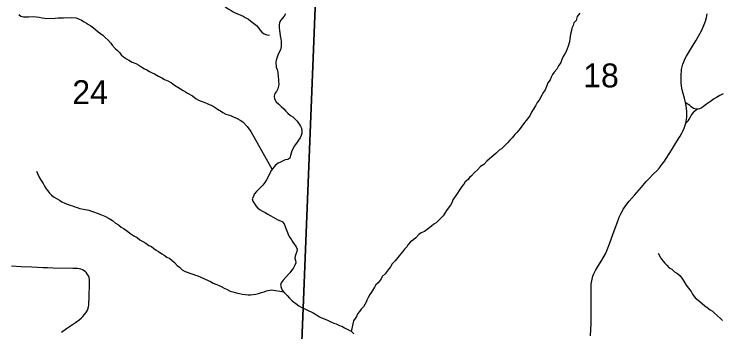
# Model space of a CAD drawing. Extents: x -3.3 to 34, y 0 to 56.8.
# Drawn here: x -1.801 to -0.562, y 32.848 to 33.404 of the extents above; entities that cross this region are included whole.
import ezdxf

# ---------------------------------------------------------------- set-up
doc = ezdxf.new("R2010")
doc.units = 0
for name, color, linetype in [('GM_X_Corporation', 7, 'Continuous'), ('GM_X_County_Road', 7, 'Continuous'), ('GM_X_Section_Text', 7, 'Continuous'), ('GM_X_Township_Road', 7, 'Continuous'), ('GT_Project_Soil_Layers', 7, 'Continuous')]:
    doc.layers.add(name, color=color, linetype=linetype)

msp = doc.modelspace()

# ---------------------------------------------------------------- linework, layer by layer
at = {"layer": 'GM_X_Corporation'}
for points in [[(-2.2828, 33.7097), (-1.2628, 33.6793), (-1.3017, 32.7146), (-2.3198, 32.7465)], [(-1.2628, 33.6793), (-0.2543, 33.6541), (-0.2878, 32.6826), (-1.3017, 32.7146)]]:
    msp.add_lwpolyline(points, close=True, dxfattribs=at)
at = {"layer": 'GM_X_County_Road'}
msp.add_lwpolyline([(-0.7912, 32.8413), (-0.7905, 32.8627), (-0.7906, 32.9051), (-0.7905, 32.9233), (-0.7904, 32.9274), (-0.7902, 32.9318), (-0.7899, 32.9347), (-0.7888, 32.9404), (-0.7873, 32.9455), (-0.7855, 32.9501), (-0.7826, 32.9555), (-0.7757, 32.9671), (-0.7719, 32.9735), (-0.7655, 32.9848), (-0.7622, 32.9921), (-0.7581, 33.0023), (-0.7518, 33.0205), (-0.7455, 33.0375), (-0.741, 33.0489), (-0.7383, 33.0547), (-0.7363, 33.059), (-0.734, 33.0632), (-0.7321, 33.0661), (-0.7299, 33.0693), (-0.7239, 33.0768), (-0.7146, 33.0877), (-0.7023, 33.1018), (-0.6939, 33.1114), (-0.6889, 33.1169), (-0.6812, 33.1246), (-0.6756, 33.1301), (-0.6709, 33.1354), (-0.6666, 33.1411), (-0.6633, 33.1455), (-0.6496, 33.1664), (-0.6408, 33.1808), (-0.6343, 33.191), (-0.6315, 33.1958), (-0.6296, 33.1996), (-0.6274, 33.2047), (-0.6255, 33.2102), (-0.6245, 33.2137), (-0.6238, 33.2173), (-0.6234, 33.2205), (-0.623, 33.2241), (-0.6227, 33.2291), (-0.6229, 33.2341), (-0.6235, 33.2394), (-0.6241, 33.2443), (-0.6252, 33.2496), (-0.6271, 33.2575), (-0.6294, 33.2655), (-0.631, 33.2719), (-0.6316, 33.2746), (-0.6322, 33.2789), (-0.6328, 33.2842), (-0.633, 33.2895), (-0.6328, 33.2991), (-0.6323, 33.3039), (-0.6319, 33.3075), (-0.631, 33.3122), (-0.6297, 33.3167), (-0.6283, 33.3208), (-0.6267, 33.3242), (-0.6232, 33.3311), (-0.6144, 33.3457), (-0.6073, 33.3577), (-0.6023, 33.3661), (-0.5994, 33.3714), (-0.5973, 33.3754), (-0.5936, 33.3836), (-0.5904, 33.3921), (-0.5885, 33.3986), (-0.5873, 33.4047)], dxfattribs=at)
at = {"layer": 'GM_X_Township_Road'}
for points in [[(-0.5593, 33.2647), (-0.5649, 33.2621), (-0.571, 33.2587), (-0.5763, 33.2554), (-0.5813, 33.2518), (-0.5884, 33.2466), (-0.5958, 33.2411), (-0.598, 33.2399), (-0.6006, 33.2388), (-0.6029, 33.2383), (-0.6052, 33.238)], [(-0.6052, 33.238), (-0.6086, 33.2384), (-0.611, 33.2393), (-0.6129, 33.2403), (-0.615, 33.242), (-0.6175, 33.2443), (-0.6197, 33.2461), (-0.622, 33.2476), (-0.6252, 33.2496)], [(-0.6245, 33.2137), (-0.6205, 33.2177), (-0.6186, 33.2204), (-0.6164, 33.2247), (-0.615, 33.2272), (-0.6134, 33.2296), (-0.6113, 33.2322), (-0.6093, 33.2343), (-0.6052, 33.238)], [(-1.7177, 32.8474), (-1.7087, 32.8541), (-1.6935, 32.8647), (-1.6871, 32.8695), (-1.6833, 32.8722), (-1.6802, 32.8752), (-1.6774, 32.8784), (-1.675, 32.8814), (-1.6728, 32.8851), (-1.6716, 32.8879), (-1.6707, 32.8922), (-1.6701, 32.8957), (-1.6697, 32.8999), (-1.6694, 32.9063), (-1.6692, 32.9151), (-1.6689, 32.9257), (-1.6686, 32.9348), (-1.6688, 32.9392), (-1.6695, 32.9433), (-1.6706, 32.9465), (-1.6721, 32.9489), (-1.6738, 32.9514), (-1.6756, 32.9532), (-1.6783, 32.9553), (-1.6812, 32.9568), (-1.6839, 32.9578), (-1.6868, 32.9585), (-1.6897, 32.959), (-1.6977, 32.9594), (-1.7331, 32.9598), (-1.7422, 32.9601), (-1.7497, 32.9604), (-1.7697, 32.9613), (-1.7881, 32.9622), (-1.8053, 32.963)]]:
    msp.add_lwpolyline(points, dxfattribs=at)
at = {"layer": 'GT_Project_Soil_Layers'}
for points in [[(-1.4349, 33.4207), (-1.4299, 33.4166), (-1.4257, 33.414), (-1.4207, 33.411), (-1.4169, 33.4084), (-1.4123, 33.4062), (-1.4078, 33.4044), (-1.404, 33.4029), (-1.3998, 33.4011), (-1.3959, 33.3988), (-1.3906, 33.3959), (-1.386, 33.3921), (-1.3814, 33.3888), (-1.3764, 33.3847), (-1.3729, 33.3805), (-1.3702, 33.3768), (-1.3671, 33.3727), (-1.3629, 33.3697), (-1.3584, 33.3682), (-1.3538, 33.3675)], [(-1.7926, 33.4036), (-1.7888, 33.401), (-1.7842, 33.3995), (-1.7793, 33.3996), (-1.7755, 33.4), (-1.7668, 33.4002), (-1.7619, 33.3995), (-1.7569, 33.3992), (-1.7516, 33.3981), (-1.747, 33.3974), (-1.7432, 33.3971), (-1.7288, 33.3973), (-1.7235, 33.3977), (-1.719, 33.3978), (-1.7141, 33.3982), (-1.7, 33.3984), (-1.6921, 33.3978), (-1.6879, 33.3963), (-1.6829, 33.3941), (-1.6779, 33.3911), (-1.6741, 33.3885), (-1.6703, 33.3863), (-1.6661, 33.3837), (-1.6619, 33.3807), (-1.658, 33.3777), (-1.6534, 33.3736), (-1.6492, 33.3706), (-1.6454, 33.3677), (-1.6415, 33.3635), (-1.6358, 33.3587), (-1.6312, 33.3538), (-1.6288, 33.35), (-1.6235, 33.3444), (-1.6196, 33.3407), (-1.6154, 33.3369), (-1.6131, 33.3332), (-1.6092, 33.3298), (-1.6039, 33.3261), (-1.6, 33.3238), (-1.5939, 33.3205), (-1.5878, 33.3179), (-1.5825, 33.315), (-1.5771, 33.3116), (-1.5725, 33.3087), (-1.5683, 33.3072), (-1.5634, 33.3042), (-1.5588, 33.3016), (-1.555, 33.3002), (-1.5477, 33.2961), (-1.542, 33.2927), (-1.5374, 33.2901), (-1.5317, 33.2876), (-1.5252, 33.2839), (-1.5198, 33.2801), (-1.5141, 33.2768), (-1.5091, 33.2734), (-1.5049, 33.2709), (-1.5007, 33.2686), (-1.4969, 33.266), (-1.4881, 33.2612), (-1.4819, 33.2564), (-1.4777, 33.2541), (-1.4732, 33.2523), (-1.4694, 33.2508), (-1.4636, 33.2483), (-1.4594, 33.2464), (-1.4556, 33.2449), (-1.4507, 33.2424), (-1.4468, 33.2401), (-1.443, 33.2371), (-1.4392, 33.2353), (-1.4354, 33.2323), (-1.43, 33.2294), (-1.4262, 33.2279), (-1.422, 33.2268), (-1.4182, 33.225), (-1.4136, 33.2235), (-1.409, 33.2209), (-1.4048, 33.2187), (-1.4002, 33.2157), (-1.3925, 33.2075), (-1.3864, 33.1992), (-1.3489, 33.1325)], [(-1.3255, 33.4048), (-1.3281, 33.4009), (-1.334, 33.3932), (-1.3363, 33.3894), (-1.3366, 33.3856), (-1.3369, 33.3807), (-1.3361, 33.3757), (-1.3353, 33.3716), (-1.3348, 33.3663), (-1.3336, 33.361), (-1.3332, 33.3568), (-1.3331, 33.3522), (-1.3334, 33.3477), (-1.3345, 33.342), (-1.3371, 33.337), (-1.3389, 33.3328), (-1.3404, 33.329), (-1.3418, 33.324), (-1.3425, 33.3202), (-1.3416, 33.3115), (-1.3401, 33.3073), (-1.3392, 33.3024), (-1.3384, 33.2948), (-1.3379, 33.2903), (-1.3375, 33.2865), (-1.3374, 33.2819), (-1.3378, 33.2781), (-1.3392, 33.2735), (-1.3414, 33.2693), (-1.3444, 33.2655), (-1.3455, 33.2609), (-1.3447, 33.2564), (-1.3416, 33.2507), (-1.337, 33.2466), (-1.3331, 33.2425), (-1.3285, 33.2384), (-1.325, 33.2346), (-1.3212, 33.2309), (-1.3166, 33.2271), (-1.3128, 33.2245), (-1.3051, 33.217), (-1.3016, 33.2121), (-1.2993, 33.2084), (-1.2977, 33.2046), (-1.2969, 33.2008), (-1.2972, 33.1963), (-1.2983, 33.1921), (-1.3001, 33.1879), (-1.3027, 33.1836), (-1.3064, 33.1783), (-1.3102, 33.1733), (-1.312, 33.1691), (-1.3142, 33.1653), (-1.3157, 33.1611), (-1.3168, 33.1569), (-1.3178, 33.1523), (-1.3216, 33.15), (-1.3261, 33.1491), (-1.3299, 33.1479), (-1.3341, 33.1452), (-1.3382, 33.1433), (-1.3431, 33.1398), (-1.3505, 33.1306), (-1.3564, 33.1183), (-1.359, 33.1145), (-1.362, 33.1095), (-1.3653, 33.1049), (-1.3691, 33.1007), (-1.3728, 33.0976), (-1.3762, 33.0937), (-1.3803, 33.0891), (-1.3818, 33.0853), (-1.384, 33.0811), (-1.3828, 33.0773), (-1.3805, 33.0736), (-1.3777, 33.069), (-1.3739, 33.0645), (-1.3701, 33.0619), (-1.3659, 33.0593), (-1.3613, 33.0571), (-1.3563, 33.0541), (-1.351, 33.0512), (-1.3433, 33.0467), (-1.3391, 33.0445)], [(-0.8102, 33.4062), (-0.8147, 33.4001), (-0.8165, 33.3936), (-0.8206, 33.3894), (-0.8216, 33.3844), (-0.8239, 33.3799), (-0.8246, 33.376), (-0.8264, 33.3696), (-0.8274, 33.3612), (-0.8285, 33.3559), (-0.8306, 33.3482), (-0.8339, 33.3391), (-0.8365, 33.3349), (-0.8391, 33.3303), (-0.8417, 33.3249), (-0.8435, 33.3196), (-0.8476, 33.3142), (-0.8502, 33.3081), (-0.855, 33.3027), (-0.858, 33.2985), (-0.8606, 33.2943), (-0.862, 33.2893), (-0.8661, 33.2843), (-0.8676, 33.2805), (-0.8709, 33.2721), (-0.875, 33.2663), (-0.8768, 33.2625), (-0.8813, 33.2541), (-0.8846, 33.2495), (-0.8876, 33.2437), (-0.8917, 33.2376), (-0.8946, 33.233), (-0.898, 33.2265), (-0.9043, 33.2184), (-0.9069, 33.2146), (-0.9166, 33.2019), (-0.9203, 33.1973), (-0.9237, 33.1935), (-0.9289, 33.1877), (-0.9326, 33.1839), (-0.9368, 33.1792), (-0.9409, 33.175), (-0.9476, 33.1688), (-0.9514, 33.1665), (-0.957, 33.1604), (-0.9641, 33.1546), (-0.9686, 33.1511), (-0.9731, 33.1468), (-0.9783, 33.1414), (-0.9843, 33.1376), (-0.9896, 33.1318), (-0.9944, 33.1272), (-0.9997, 33.1214), (-1.0034, 33.1187), (-1.0056, 33.1149), (-1.0109, 33.1106), (-1.0131, 33.1068), (-1.0165, 33.1025), (-1.0217, 33.0956), (-1.0243, 33.091), (-1.0324, 33.0795), (-1.0339, 33.075), (-1.0369, 33.07), (-1.0406, 33.065), (-1.0439, 33.0604), (-1.0465, 33.0558), (-1.0495, 33.0512), (-1.0532, 33.0477), (-1.057, 33.0435), (-1.0618, 33.0389), (-1.0656, 33.0369), (-1.0701, 33.0331), (-1.075, 33.0292), (-1.0821, 33.0242), (-1.0881, 33.0214), (-1.0919, 33.0187), (-1.0971, 33.0129), (-1.1009, 33.0098), (-1.1065, 33.0056), (-1.1106, 33.001), (-1.1128, 32.9971), (-1.117, 32.9929), (-1.1207, 32.9883), (-1.1267, 32.9814), (-1.1334, 32.9725), (-1.139, 32.9675), (-1.1419, 32.9622), (-1.1457, 32.9568), (-1.1512, 32.9499), (-1.1565, 32.9449), (-1.1583, 32.941), (-1.1635, 32.9341), (-1.1673, 32.9307), (-1.1695, 32.9265)], [(-1.7616, 33.1298), (-1.7596, 33.1253), (-1.7561, 33.1181), (-1.7534, 33.1132), (-1.7499, 33.1079), (-1.7476, 33.1034), (-1.7445, 33.0989), (-1.7417, 33.0951), (-1.739, 33.091), (-1.7352, 33.0876), (-1.7306, 33.0839), (-1.7252, 33.0809), (-1.7214, 33.0787), (-1.7172, 33.0761), (-1.7119, 33.0735), (-1.7081, 33.072), (-1.7027, 33.0702), (-1.6985, 33.0691), (-1.6943, 33.0673), (-1.6902, 33.0662), (-1.6856, 33.0644), (-1.6795, 33.0633), (-1.6696, 33.0612), (-1.6654, 33.0593), (-1.6616, 33.0583), (-1.6555, 33.0561), (-1.6479, 33.0531), (-1.6418, 33.0505), (-1.6342, 33.0469), (-1.6284, 33.0431), (-1.623, 33.0387), (-1.6177, 33.0357), (-1.6135, 33.0316), (-1.6093, 33.0293), (-1.6047, 33.0264), (-1.5981, 33.0208), (-1.5913, 33.0163), (-1.5855, 33.0133), (-1.5806, 33.0096), (-1.5752, 33.0063), (-1.5699, 33.0037), (-1.5649, 32.9996), (-1.5603, 32.9974), (-1.5561, 32.994), (-1.5519, 32.9914), (-1.5477, 32.9888), (-1.5423, 32.9851), (-1.5381, 32.9825), (-1.5331, 32.9787), (-1.5281, 32.9765), (-1.5239, 32.9732), (-1.5197, 32.9694), (-1.5155, 32.9646), (-1.5113, 32.9612), (-1.5063, 32.9567), (-1.5013, 32.9541), (-1.4975, 32.9527), (-1.4929, 32.9512), (-1.4876, 32.9494), (-1.483, 32.9475), (-1.4792, 32.9461), (-1.4739, 32.9442), (-1.4674, 32.9409), (-1.4609, 32.9383), (-1.4567, 32.9361), (-1.4521, 32.9335), (-1.4475, 32.9317), (-1.4418, 32.9291), (-1.4372, 32.9273), (-1.433, 32.9247), (-1.4277, 32.9225), (-1.4223, 32.9195), (-1.4178, 32.9181), (-1.4136, 32.917), (-1.4098, 32.9159), (-1.406, 32.9152), (-1.401, 32.9145), (-1.3957, 32.9134), (-1.3908, 32.9131), (-1.3866, 32.9132), (-1.3824, 32.9136), (-1.3775, 32.9144), (-1.373, 32.9153), (-1.3673, 32.9169), (-1.3628, 32.9184), (-1.359, 32.92), (-1.3499, 32.9217), (-1.3286, 32.9182)], [(-1.3391, 33.0445), (-1.3345, 33.0427), (-1.3307, 33.0408), (-1.3276, 33.0371), (-1.3261, 33.0329), (-1.3249, 33.0291), (-1.3233, 33.0253), (-1.3205, 33.0174), (-1.3178, 33.0136), (-1.3151, 33.0095), (-1.3128, 33.005), (-1.3097, 33.0012), (-1.307, 32.9971), (-1.305, 32.9929), (-1.3057, 32.9887), (-1.3076, 32.9845), (-1.3087, 32.9807), (-1.309, 32.9769), (-1.3078, 32.9731), (-1.3074, 32.969), (-1.3092, 32.9648), (-1.3114, 32.9602), (-1.3181, 32.9517), (-1.3252, 32.9437), (-1.3297, 32.9387), (-1.333, 32.9341), (-1.3341, 32.9299), (-1.3329, 32.9261), (-1.3314, 32.9215), (-1.3271, 32.9163), (-1.3225, 32.9118), (-1.3183, 32.9073), (-1.3136, 32.9028), (-1.3075, 32.8979), (-1.3021, 32.8938), (-1.2983, 32.8916), (-1.277, 32.8813), (-1.2712, 32.8779), (-1.2659, 32.8746), (-1.2598, 32.8716), (-1.2559, 32.8706), (-1.2506, 32.868), (-1.2464, 32.8657), (-1.2407, 32.8632), (-1.2369, 32.8621), (-1.2308, 32.8595), (-1.2266, 32.858), (-1.222, 32.8554), (-1.2178, 32.8529), (-1.214, 32.851), (-1.2101, 32.8488), (-1.2059, 32.8447)], [(-0.6732, 32.9862), (-0.6682, 32.9771), (-0.6647, 32.9726), (-0.6612, 32.9685), (-0.6577, 32.9647), (-0.6535, 32.9606), (-0.6493, 32.958), (-0.6443, 32.9535), (-0.6393, 32.9502), (-0.6344, 32.9464), (-0.6313, 32.9423), (-0.6282, 32.937), (-0.6239, 32.9299), (-0.6197, 32.9246), (-0.6154, 32.9186), (-0.6131, 32.9141), (-0.608, 32.9077), (-0.6027, 32.9036), (-0.5962, 32.898), (-0.5912, 32.8939), (-0.5873, 32.8909), (-0.582, 32.8868), (-0.5781, 32.8842), (-0.5743, 32.8812), (-0.5639, 32.8718), (-0.5605, 32.8681)], [(-1.1695, 32.9265), (-1.1747, 32.918), (-1.1777, 32.9138), (-1.1806, 32.9084), (-1.1832, 32.9039), (-1.1843, 32.9), (-1.1891, 32.892), (-1.1929, 32.8881), (-1.1958, 32.8839), (-1.1988, 32.8801), (-1.2007, 32.8763), (-1.2036, 32.8717), (-1.2062, 32.8678), (-1.2105, 32.849)]]:
    msp.add_lwpolyline(points, dxfattribs=at)

# ---------------------------------------------------------------- texts
at = {"layer": 'GM_X_Section_Text'}
for s, p in [('18', (-0.8042, 33.2762)), ('24', (-1.6988, 33.2469))]:
    msp.add_text(s, height=0.04186, rotation=0, dxfattribs=at).set_placement(p)

doc.saveas('drawing.dxf')
